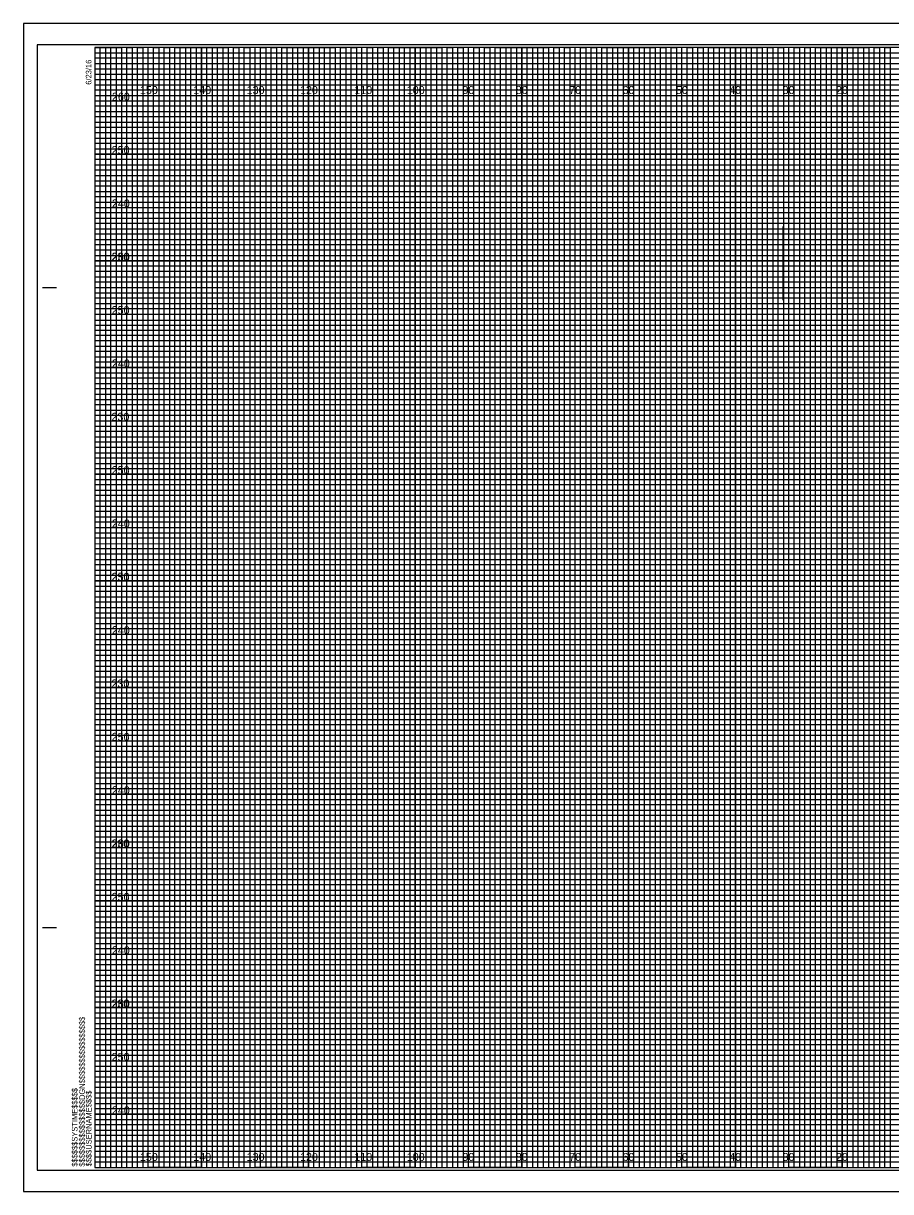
# Model space of a CAD drawing. Extents: x -13 to 359, y -5 to 2854.
# Drawn here: x -13.4 to 149.1, y 215.5 to 434.5 of the extents above; entities that cross this region are included whole.
import ezdxf

# ---------------------------------------------------------------- set-up
doc = ezdxf.new("R2010")
doc.units = 0
for name, color, linetype in [('Exist Cross Section Cell', 7, 'Continuous'), ('Exist XS Ground Line', 7, 'Continuous'), ('Prop CMT Concrete Structures', 7, 'Continuous'), ('Prop CMT DNC', 7, 'Continuous'), ('Prop CMT Pvmt Course 1', 7, 'Continuous'), ('Prop CMT Pvmt Course 1 CG', 7, 'Continuous'), ('Prop CMT Pvmt Course 2', 7, 'Continuous'), ('Prop CMT Pvmt Wedge Surface 1', 7, 'Continuous'), ('Prop CMT Shear Line', 7, 'Continuous'), ('Prop CMT Slope Grass', 7, 'Continuous'), ('Prop CMT Subgrade Earthwork', 7, 'Continuous'), ('Scratch_Level_0', 7, 'Continuous')]:
    doc.layers.add(name, color=color, linetype=linetype)

msp = doc.modelspace()

# ---------------------------------------------------------------- linework, layer by layer
at = {"layer": 'Exist XS Ground Line'}
for p, q in [((10, 430), (0, 430)), ((10, 220), (10, 430)), ((30, 430), (20, 430)), ((20, 430), (20, 220)), ((30, 220), (30, 430)), ((50, 430), (40, 430)), ((40, 430), (40, 220)), ((50, 220), (50, 430)), ((70, 430), (60, 430)), ((60, 430), (60, 220)), ((70, 220), (70, 430)), ((90, 430), (80, 430)), ((80, 430), (80, 220)), ((90, 220), (90, 430)), ((110, 430), (100, 430)), ((100, 430), (100, 220)), ((110, 220), (110, 430)), ((130, 430), (120, 430)), ((120, 430), (120, 220)), ((130, 220), (130, 430)), ((150, 430), (140, 430)), ((140, 430), (140, 220)), ((20, 220), (10, 220)), ((40, 220), (30, 220)), ((60, 220), (50, 220)), ((80, 220), (70, 220)), ((100, 220), (90, 220)), ((120, 220), (110, 220)), ((140, 220), (130, 220))]:
    msp.add_line(p, q, dxfattribs=at)
for points in [[(0, 420), (320, 420), (320, 410), (0, 410)], [(0, 400), (320, 400), (320, 390), (0, 390)], [(0, 380), (320, 380), (320, 370), (0, 370)], [(0, 360), (320, 360), (320, 350), (0, 350)], [(0, 340), (320, 340), (320, 330), (0, 330)], [(0, 320), (320, 320), (320, 310), (0, 310)], [(0, 300), (320, 300), (320, 290), (0, 290)], [(0, 280), (320, 280), (320, 270), (0, 270)], [(0, 260), (320, 260), (320, 250), (0, 250)], [(0, 240), (320, 240), (320, 230), (0, 230)]]:
    msp.add_lwpolyline(points, dxfattribs=at)
at = {"layer": 'Prop CMT Concrete Structures'}
for p, q in [((-9.8, 385), (-7.3, 385)), ((-9.7, 385), (-7.2, 385)), ((-9.8, 265), (-7.3, 265)), ((-9.7, 265), (-7.2, 265)), ((0, 220), (0, 220)), ((0, 220), (0, 220)), ((0, 220), (0, 220)), ((0, 220), (0, 220)), ((0, 220), (0, 220)), ((0, 220), (0, 220)), ((0, 220), (0, 220))]:
    msp.add_line(p, q, dxfattribs=at)
msp.add_lwpolyline([(320, 430), (0, 430), (0, 220), (320, 220)], close=True, dxfattribs=at)
at = {"layer": 'Prop CMT DNC'}
for p, q in [((323.3, 434.5), (-13.4, 434.5)), ((-13.4, 434.5), (-13.4, 215.5)), ((-13.4, 215.5), (323.3, 215.5))]:
    msp.add_line(p, q, dxfattribs=at)
at = {"layer": 'Prop CMT Pvmt Course 1'}
for p, q in [((0, 429), (260, 429)), ((260, 427.98), (0, 427.98)), ((0, 427.98), (0, 427)), ((0, 427), (260, 427)), ((260, 425.89), (0, 425.89)), ((0, 425.89), (0, 424)), ((0, 424), (320, 424))]:
    msp.add_line(p, q, dxfattribs=at)
for points in [[(0, 423), (270, 423), (320, 423), (320, 422), (0, 422)], [(0, 421), (320, 421), (320, 419), (0, 419)], [(0, 418), (320, 418), (320, 417), (0, 416.98)], [(0, 416), (320, 416), (320, 414), (0, 414)], [(0, 413), (320, 413), (320, 412), (0, 412)], [(0, 411), (320, 411), (320, 409), (0, 409)], [(0, 408), (320, 408), (320, 407), (0, 407)], [(0, 406), (320, 406), (320, 404), (0, 404)], [(0, 403), (320, 403), (320, 402), (0, 402)], [(0, 401), (320, 401), (320, 399), (0, 399)], [(0, 398), (320, 398), (320, 397), (0, 397)], [(0, 396), (320, 396), (320, 393.95), (320, 393), (320, 392), (0, 392)], [(0, 394), (320, 394), (320, 393), (0, 393)], [(0, 391), (320, 391), (320, 389), (0, 389.03)], [(0, 389.03), (320, 389), (320, 388), (0, 388)], [(0, 387), (320, 387), (320, 386), (0, 386)], [(0, 384), (320, 384), (320, 383), (0, 383)], [(0, 382), (320, 382), (320, 381), (0, 381)], [(-0.07, 378.89), (320, 378.89), (320, 377.88), (-0.07, 377.88)], [(0, 377), (320, 377), (320, 376), (0, 376)], [(0, 374), (320, 374), (320, 373), (0, 373)], [(0, 372), (320, 372), (320, 371), (0, 371)], [(0, 369), (320, 369), (320, 368), (0, 368)], [(0, 367), (320, 367), (320, 366), (0, 366)], [(0, 364), (320, 364), (320, 363), (0, 363)], [(0, 362), (320, 362), (320, 361), (0, 361)], [(0, 359), (320, 359), (319.99, 357.98), (0, 358)], [(0, 357), (320, 357), (320, 356), (0, 356)], [(0, 354), (320, 354), (320, 353), (0, 353)], [(0, 352), (320, 352), (320, 351), (0, 351)], [(0, 349), (320, 349), (320, 348), (0, 348)], [(0, 347), (320, 347), (320, 346), (0, 346)], [(0, 344), (320, 344), (320, 343), (0, 343)], [(0, 342), (320, 342), (320, 341), (0, 341)], [(0, 339), (320, 339), (320, 338), (0, 338)], [(0, 336.99), (320.07, 336.91), (320, 336), (0, 336)], [(0, 334), (320, 334), (320, 333), (0, 333)], [(0, 332), (320, 332), (320, 331), (0, 331)], [(0, 329), (320, 329), (320, 328), (0, 328)], [(0, 327), (320, 327), (320, 326), (0, 326)], [(0, 324), (320, 324), (320, 323), (0, 323)], [(0, 322), (320, 322), (320, 321), (0, 321)], [(0, 319), (320, 319), (320, 318), (0, 318)], [(0, 317), (320, 317), (320, 316), (0, 316)], [(0, 314), (320, 314), (320, 313), (0, 313)], [(0, 312), (320, 312), (320, 311), (0, 311)], [(0, 309), (320, 309), (320, 308), (0, 308)], [(0, 307), (320, 307), (320, 306), (0, 306)], [(0, 304), (320, 304), (320, 303), (0, 303)], [(0, 302), (320, 302), (320, 301), (0, 301)], [(0, 299), (320, 299), (319.99, 297.98), (0, 298)], [(0, 297), (320, 297), (320, 296), (0, 296)], [(0, 294), (320, 294), (320, 293), (0, 293)], [(0, 292), (320, 292), (320, 291), (0, 291)], [(0, 289), (320, 289), (320, 288), (0, 288)], [(0, 287), (320, 287), (320, 286), (0, 286)], [(0, 284), (320, 284), (320, 283), (0, 283)], [(0, 282), (320, 282), (320, 281), (0, 281)], [(0, 279), (320, 279), (320, 278), (0, 278)], [(0, 276.99), (320.07, 276.91), (320, 276), (0, 276)], [(0, 274), (320, 274), (320, 273), (0, 273)], [(0, 272), (320, 272), (320, 271), (0, 271)], [(0, 269), (320, 269), (320, 268), (0, 268)], [(0, 267), (320, 267), (320, 266), (0, 266)], [(0, 264), (320, 264), (320, 263), (0, 263)], [(0, 262), (320, 262), (320, 261), (0, 261)], [(0, 259), (320, 259), (320, 258), (0, 258)], [(0, 257), (320, 257), (320, 256), (0, 256)], [(0, 254), (320, 254), (320, 253), (0, 253)], [(0, 252), (320, 252), (320, 251), (0, 251)], [(0, 249), (320, 249), (320, 248), (0, 248)], [(0, 247), (320, 247), (320, 246), (0, 246)], [(0, 244), (320, 244), (320, 243), (0, 243)], [(0, 242), (320, 242), (320, 241), (0, 241)], [(0, 239), (320, 239), (320, 238), (0, 238)], [(0, 237), (320, 237), (320, 236), (0, 236)], [(0, 234), (320, 234), (320, 233), (0, 233)], [(0, 232), (320, 232), (320, 231), (0, 231)], [(0, 229), (320, 229), (320, 228), (0, 228)], [(0, 227), (320, 227), (320, 226), (0, 226)], [(0, 224), (320, 224), (320, 223), (0, 223)], [(0, 222), (320, 222), (320, 221), (0, 221)]]:
    msp.add_lwpolyline(points, dxfattribs=at)
at = {"layer": 'Prop CMT Pvmt Course 1 CG'}
for points in [[(0, 220), (1, 220), (1, 430), (2, 430), (2, 220)], [(2, 220), (3, 220), (3, 430), (4, 430), (4, 220)], [(5, 220), (6, 220), (6, 430), (7, 430), (7, 220)], [(7, 220), (8, 220), (8, 430), (9, 430), (9, 220)], [(10, 220), (11, 220), (11, 430), (12, 430), (12, 220)], [(12, 220), (13, 220), (13, 430), (14, 430), (14, 220)], [(15, 220), (16, 220), (16, 430), (17, 430), (17, 220)], [(17, 220), (18, 220), (18, 430), (19, 430), (19, 220)], [(20, 220), (21, 220), (21, 430), (22, 430), (22, 220)], [(22, 220), (23, 220), (23, 430), (24, 430), (24, 220)], [(25, 220), (26, 220), (26, 430), (27, 430), (27, 220)], [(27, 220), (28, 220), (28, 430), (29, 430), (29, 220)], [(30, 220), (31, 220), (31, 430), (32, 430), (32, 220)], [(32, 220), (33, 220), (33, 430), (34, 430), (34, 220)], [(35, 220), (36, 220), (36, 430), (37, 430), (37, 220)], [(37, 220), (38, 220), (38, 430), (39, 430), (39, 220)], [(40, 220), (41, 220), (41, 430), (42, 430), (42, 220)], [(42, 220), (43, 220), (43, 430), (44, 430), (44, 220)], [(45, 220), (46, 220), (46, 430), (47, 430), (47, 220)], [(47, 220), (48, 220), (48, 430), (49, 430), (49, 220)], [(50, 220), (51, 220), (51, 430), (52, 430), (52, 220)], [(52, 220), (53, 220), (53, 430), (54, 430), (54, 220)], [(55, 220), (56, 220), (56, 430), (57, 430), (57, 220)], [(57, 220), (58, 220), (58, 430), (59, 430), (59, 220)], [(60, 220), (61, 220), (61, 430), (62, 430), (62, 220)], [(62, 220), (63, 220), (63, 430), (64, 430), (64, 220)], [(65, 220), (66, 220), (66, 430), (67, 430), (67, 220)], [(67, 220), (68, 220), (68, 430), (69, 430), (69, 220)], [(70, 220), (71, 220), (71, 430), (72, 430), (72, 220)], [(72, 220), (73, 220), (73, 430), (74, 430), (74, 220)], [(75, 220), (76, 220), (76, 430), (77, 430), (77, 220)], [(77, 220), (78, 220), (78, 430), (79, 430), (79, 220)], [(80, 220), (81, 220), (81, 430), (82, 430), (82, 220)], [(82, 220), (83, 220), (83, 430), (84, 430), (84, 220)], [(85, 220), (86, 220), (86, 430), (87, 430), (87, 220)], [(87, 220), (88, 220), (88, 430), (89, 430), (89, 220)], [(90, 220), (91, 220), (91, 430), (92, 430), (92, 220)], [(92, 220), (93, 220), (93, 430), (94, 430), (94, 220)], [(95, 220), (96, 220), (96, 430), (97, 430), (97, 220)], [(97, 220), (98, 220), (98, 430), (99, 430), (99, 220)], [(100, 220), (101, 220), (101, 430), (102, 430), (102, 220)], [(102, 220), (103, 220), (103, 430), (104, 430), (104, 220)], [(105, 220), (106, 220), (106, 430), (107, 430), (107, 220)], [(107, 220), (108, 220), (108, 430), (109, 430), (109, 220)], [(110, 220), (111, 220), (111, 430), (112, 430), (112, 220)], [(112, 220), (113, 220), (113, 430), (114, 430), (114, 220)], [(115, 220), (116, 220), (116, 430), (117, 430), (117, 220)], [(117, 220), (118, 220), (118, 430), (119, 430), (119, 220)], [(120, 220), (121, 220), (121, 430), (122, 430), (122, 220)], [(122, 220), (123, 220), (123, 430), (124, 430), (124, 220)], [(125, 220), (126, 220), (126, 430), (127, 430), (127, 220)], [(127, 220), (128, 220), (128, 430), (129, 430), (129, 220)], [(130, 220), (131, 220), (131, 430), (132, 430), (132, 220)], [(132, 220), (133, 220), (133, 430), (134, 430), (134, 220)], [(135, 220), (136, 220), (136, 430), (137, 430), (137, 220)], [(137, 220), (138, 220), (138, 430), (139, 430), (139, 220)], [(140, 220), (141, 220), (141, 430), (142, 430), (142, 220)], [(142, 220), (143, 220), (143, 430), (144, 430), (144, 220)], [(145, 220), (146, 220), (146, 430), (147, 430), (147, 220)], [(147, 220), (148, 220), (148, 430), (149, 430), (149, 220)]]:
    msp.add_lwpolyline(points, dxfattribs=at)
at = {"layer": 'Prop CMT Pvmt Wedge Surface 1'}
msp.add_line((128.94, 382.63), (128.94, 396.43), dxfattribs=at)
at = {"layer": 'Prop CMT Shear Line'}
for p, q in [((10, 220), (10, 430)), ((20, 220), (20, 430)), ((30, 220), (30, 430)), ((40, 220), (40, 430)), ((50, 220), (50, 430)), ((60, 220), (60, 430)), ((70, 220), (70, 430)), ((80, 220), (80, 430)), ((90, 220), (90, 430)), ((100, 220), (100, 430)), ((110, 220), (110, 430)), ((120, 220), (120, 430)), ((130, 220), (130, 430)), ((140, 220), (140, 430)), ((0, 420), (320, 420)), ((0, 410), (320, 410)), ((0, 400), (320, 400)), ((0, 390), (320, 390)), ((0, 380), (320, 380)), ((0, 370), (320, 370)), ((0, 360), (320, 360)), ((0, 350), (320, 350)), ((0, 340), (320, 340)), ((0, 330), (320, 330)), ((0, 320), (320, 320)), ((0, 310), (320, 310)), ((0, 300), (320, 300)), ((0, 290), (320, 290)), ((0, 280), (320, 280)), ((0, 270), (320, 270)), ((0, 260), (320, 260)), ((0, 250), (320, 250)), ((0, 240), (320, 240)), ((0, 230), (320, 230))]:
    msp.add_line(p, q, dxfattribs=at)
at = {"layer": 'Prop CMT Slope Grass'}
msp.add_lwpolyline([(-10.8, 219.5), (322.4, 219.5), (322.4, 430.5), (-10.8, 430.5)], close=True, dxfattribs=at)
at = {"layer": 'Prop CMT Subgrade Earthwork'}
msp.add_lwpolyline([(-13.4, 215.5), (323.3, 215.5), (323.3, 434.5), (-13.4, 434.5)], close=True, dxfattribs=at)
at = {"layer": 'Scratch_Level_0'}
for points in [[(0, 430), (5, 430), (5, 220), (15, 220), (15, 430), (25, 430), (25, 220), (35, 220), (35, 430), (45, 430), (45, 220), (55, 220), (55, 430), (65, 430), (65, 220), (75, 220), (75, 430), (85, 430), (85, 220), (95, 220), (95, 430), (105, 430), (105, 220), (115, 220), (115, 430), (125, 430), (125, 220), (135, 220), (135, 430), (145, 430), (145, 220), (155, 220)], [(0, 425), (275, 425)], [(0, 405), (320, 405), (320, 415), (0, 415)], [(0, 385), (320, 385), (320, 395), (0, 395)], [(0, 365), (320, 365), (320, 375), (0, 375)], [(0, 345), (320, 345), (320, 355), (0, 355)], [(0, 325), (320, 325), (320, 335), (0, 335)], [(0, 305), (320, 305), (320, 315), (0, 315)], [(0, 285), (320, 285), (320, 295), (0, 295)], [(0, 265), (320, 265), (320, 275), (0, 275)], [(0, 245), (320, 245), (320, 255), (0, 255)], [(0, 225), (320, 225), (320, 235), (0, 235)]]:
    msp.add_lwpolyline(points, dxfattribs=at)

# ---------------------------------------------------------------- texts
at = {"layer": 'Exist Cross Section Cell'}
for s, p in [('150', (8.44, 421.25)), ('140', (18.44, 421.25)), ('130', (28.44, 421.25)), ('120', (38.44, 421.25)), ('110', (48.62, 421.25)), ('100', (58.44, 421.25)), ('90', (68.86, 421.25)), ('80', (78.86, 421.25)), ('70', (88.86, 421.25)), ('60', (98.86, 421.25)), ('50', (108.86, 421.25)), ('40', (118.86, 421.25)), ('30', (128.86, 421.25)), ('20', (138.86, 421.25)), ('150', (8.44, 221.25)), ('140', (18.44, 221.25)), ('130', (28.44, 221.25)), ('120', (38.44, 221.25)), ('110', (48.62, 221.25)), ('100', (58.44, 221.25)), ('90', (68.86, 221.25)), ('80', (78.86, 221.25)), ('70', (88.86, 221.25)), ('60', (98.86, 221.25)), ('50', (108.86, 221.25)), ('40', (118.86, 221.25)), ('30', (128.86, 221.25)), ('20', (138.86, 221.25))]:
    msp.add_text(s, height=1.5, dxfattribs=at).set_placement(p)
at = {"layer": 'Prop CMT Concrete Structures'}
for s, p in [('6/23/16', (-0.65, 423)), ('$$$$$$$$$$$$$$$$DGN$$$$$$$$$$$$$$$$', (-1.88, 220.18)), ('$$$$$$SYSTIME$$$$$', (-3.26, 220.18)), ('$$$$USERNAME$$$$', (-0.62, 220.23))]:
    msp.add_text(s, height=1.05, rotation=90, dxfattribs=at).set_placement(p)
at = {"layer": 'Prop CMT Pvmt Course 2'}
for s, p in [('260', (3.19, 420)), ('250', (3.15, 410)), ('240', (3.19, 400)), ('230', (3.11, 390)), ('260', (3.19, 390)), ('250', (3.15, 380)), ('240', (3.19, 370)), ('230', (3.11, 360)), ('250', (3.15, 350)), ('240', (3.19, 340)), ('230', (3.11, 330)), ('250', (3.15, 330)), ('240', (3.19, 320)), ('230', (3.11, 310)), ('250', (3.15, 300)), ('240', (3.19, 290)), ('230', (3.11, 280)), ('260', (3.19, 280)), ('250', (3.15, 270)), ('240', (3.19, 260)), ('230', (3.11, 250)), ('260', (3.19, 250)), ('250', (3.15, 240)), ('240', (3.19, 230))]:
    msp.add_text(s, height=1.5, dxfattribs=at).set_placement(p)

doc.saveas('drawing.dxf')
